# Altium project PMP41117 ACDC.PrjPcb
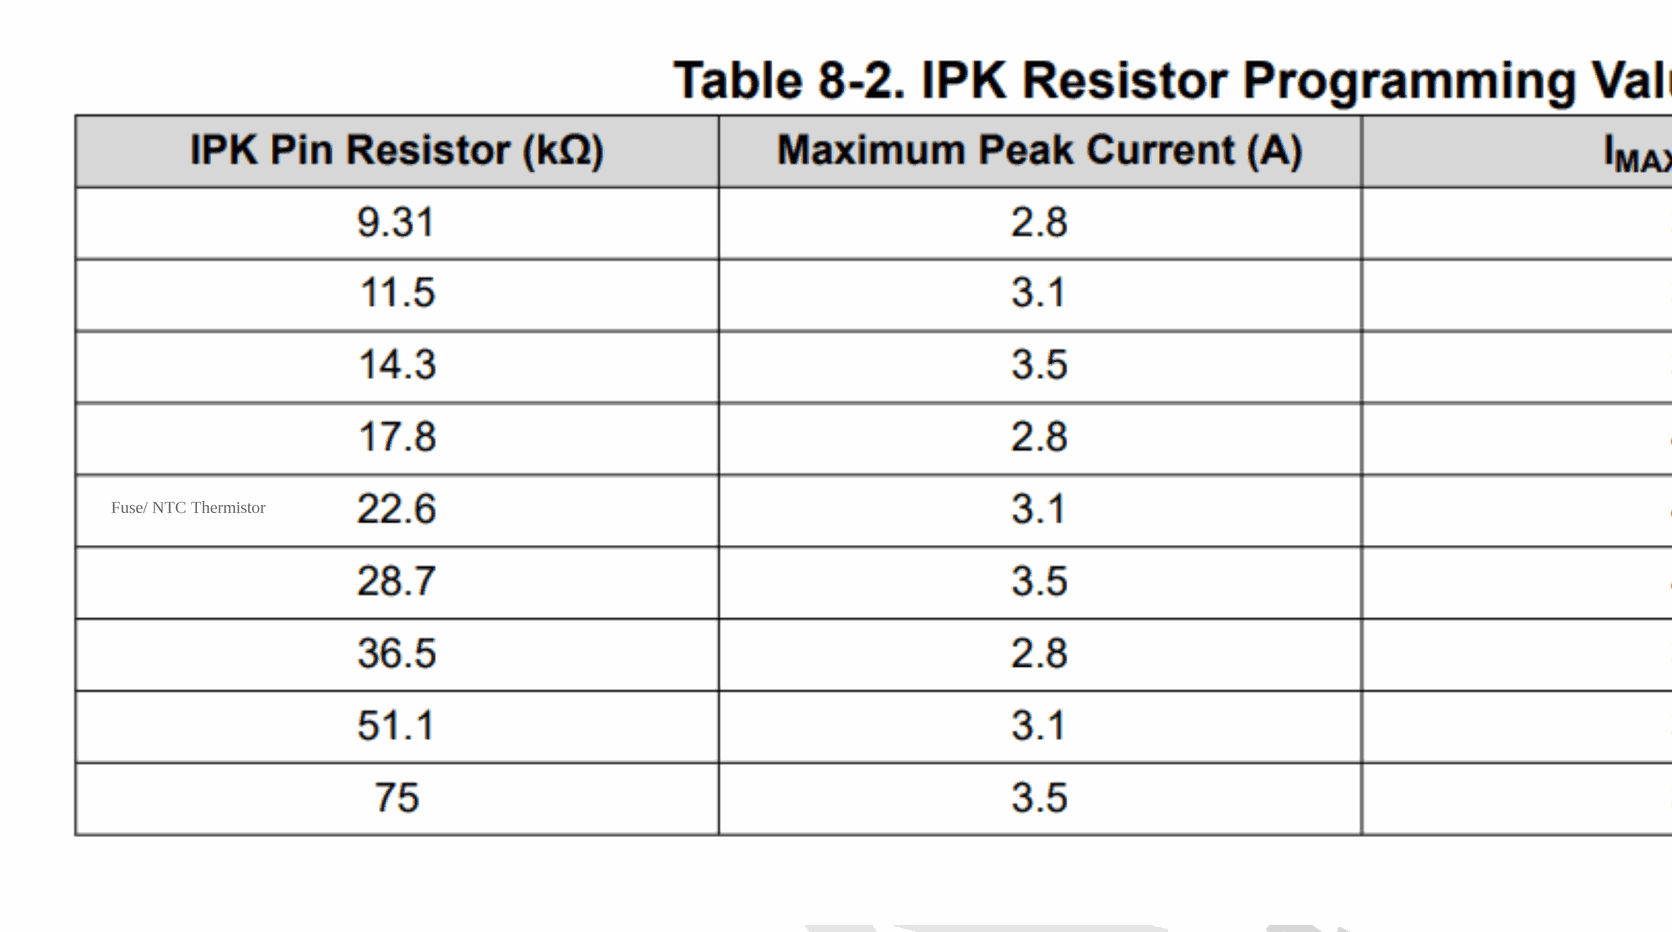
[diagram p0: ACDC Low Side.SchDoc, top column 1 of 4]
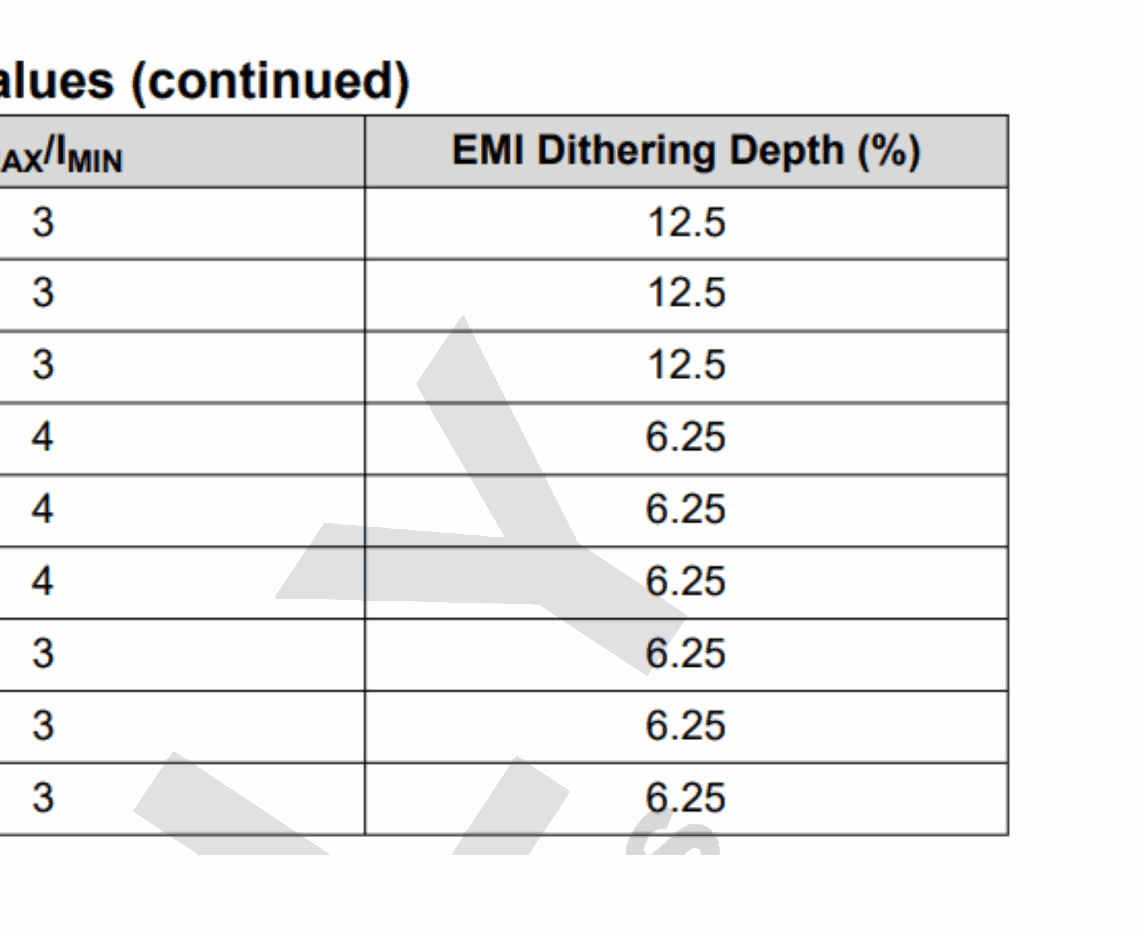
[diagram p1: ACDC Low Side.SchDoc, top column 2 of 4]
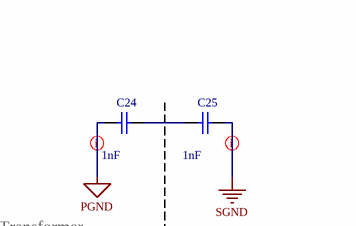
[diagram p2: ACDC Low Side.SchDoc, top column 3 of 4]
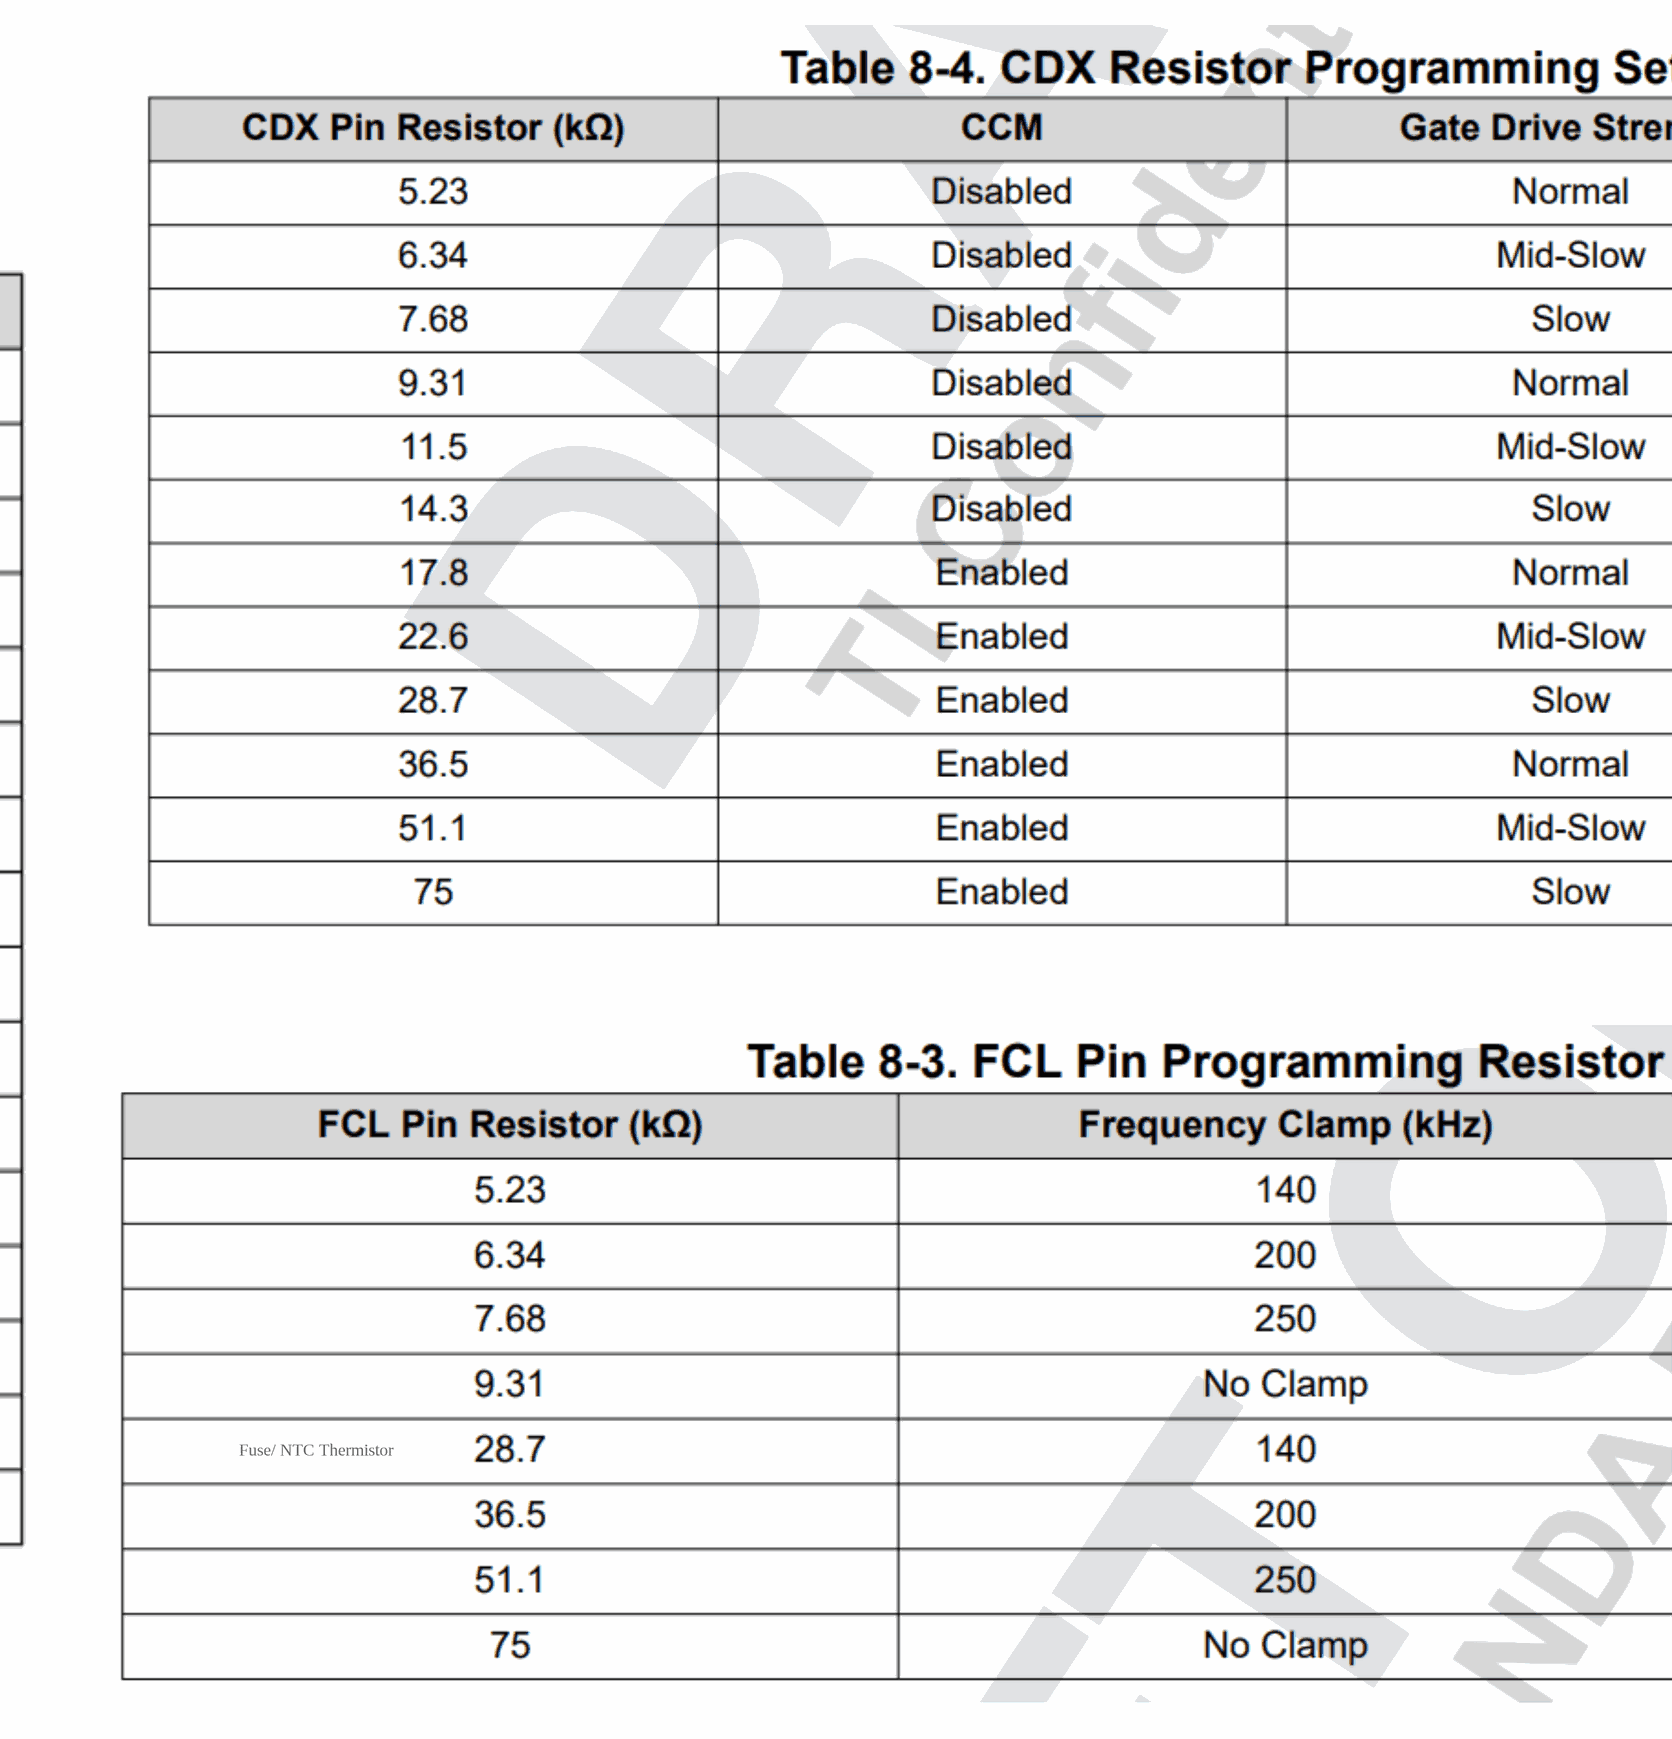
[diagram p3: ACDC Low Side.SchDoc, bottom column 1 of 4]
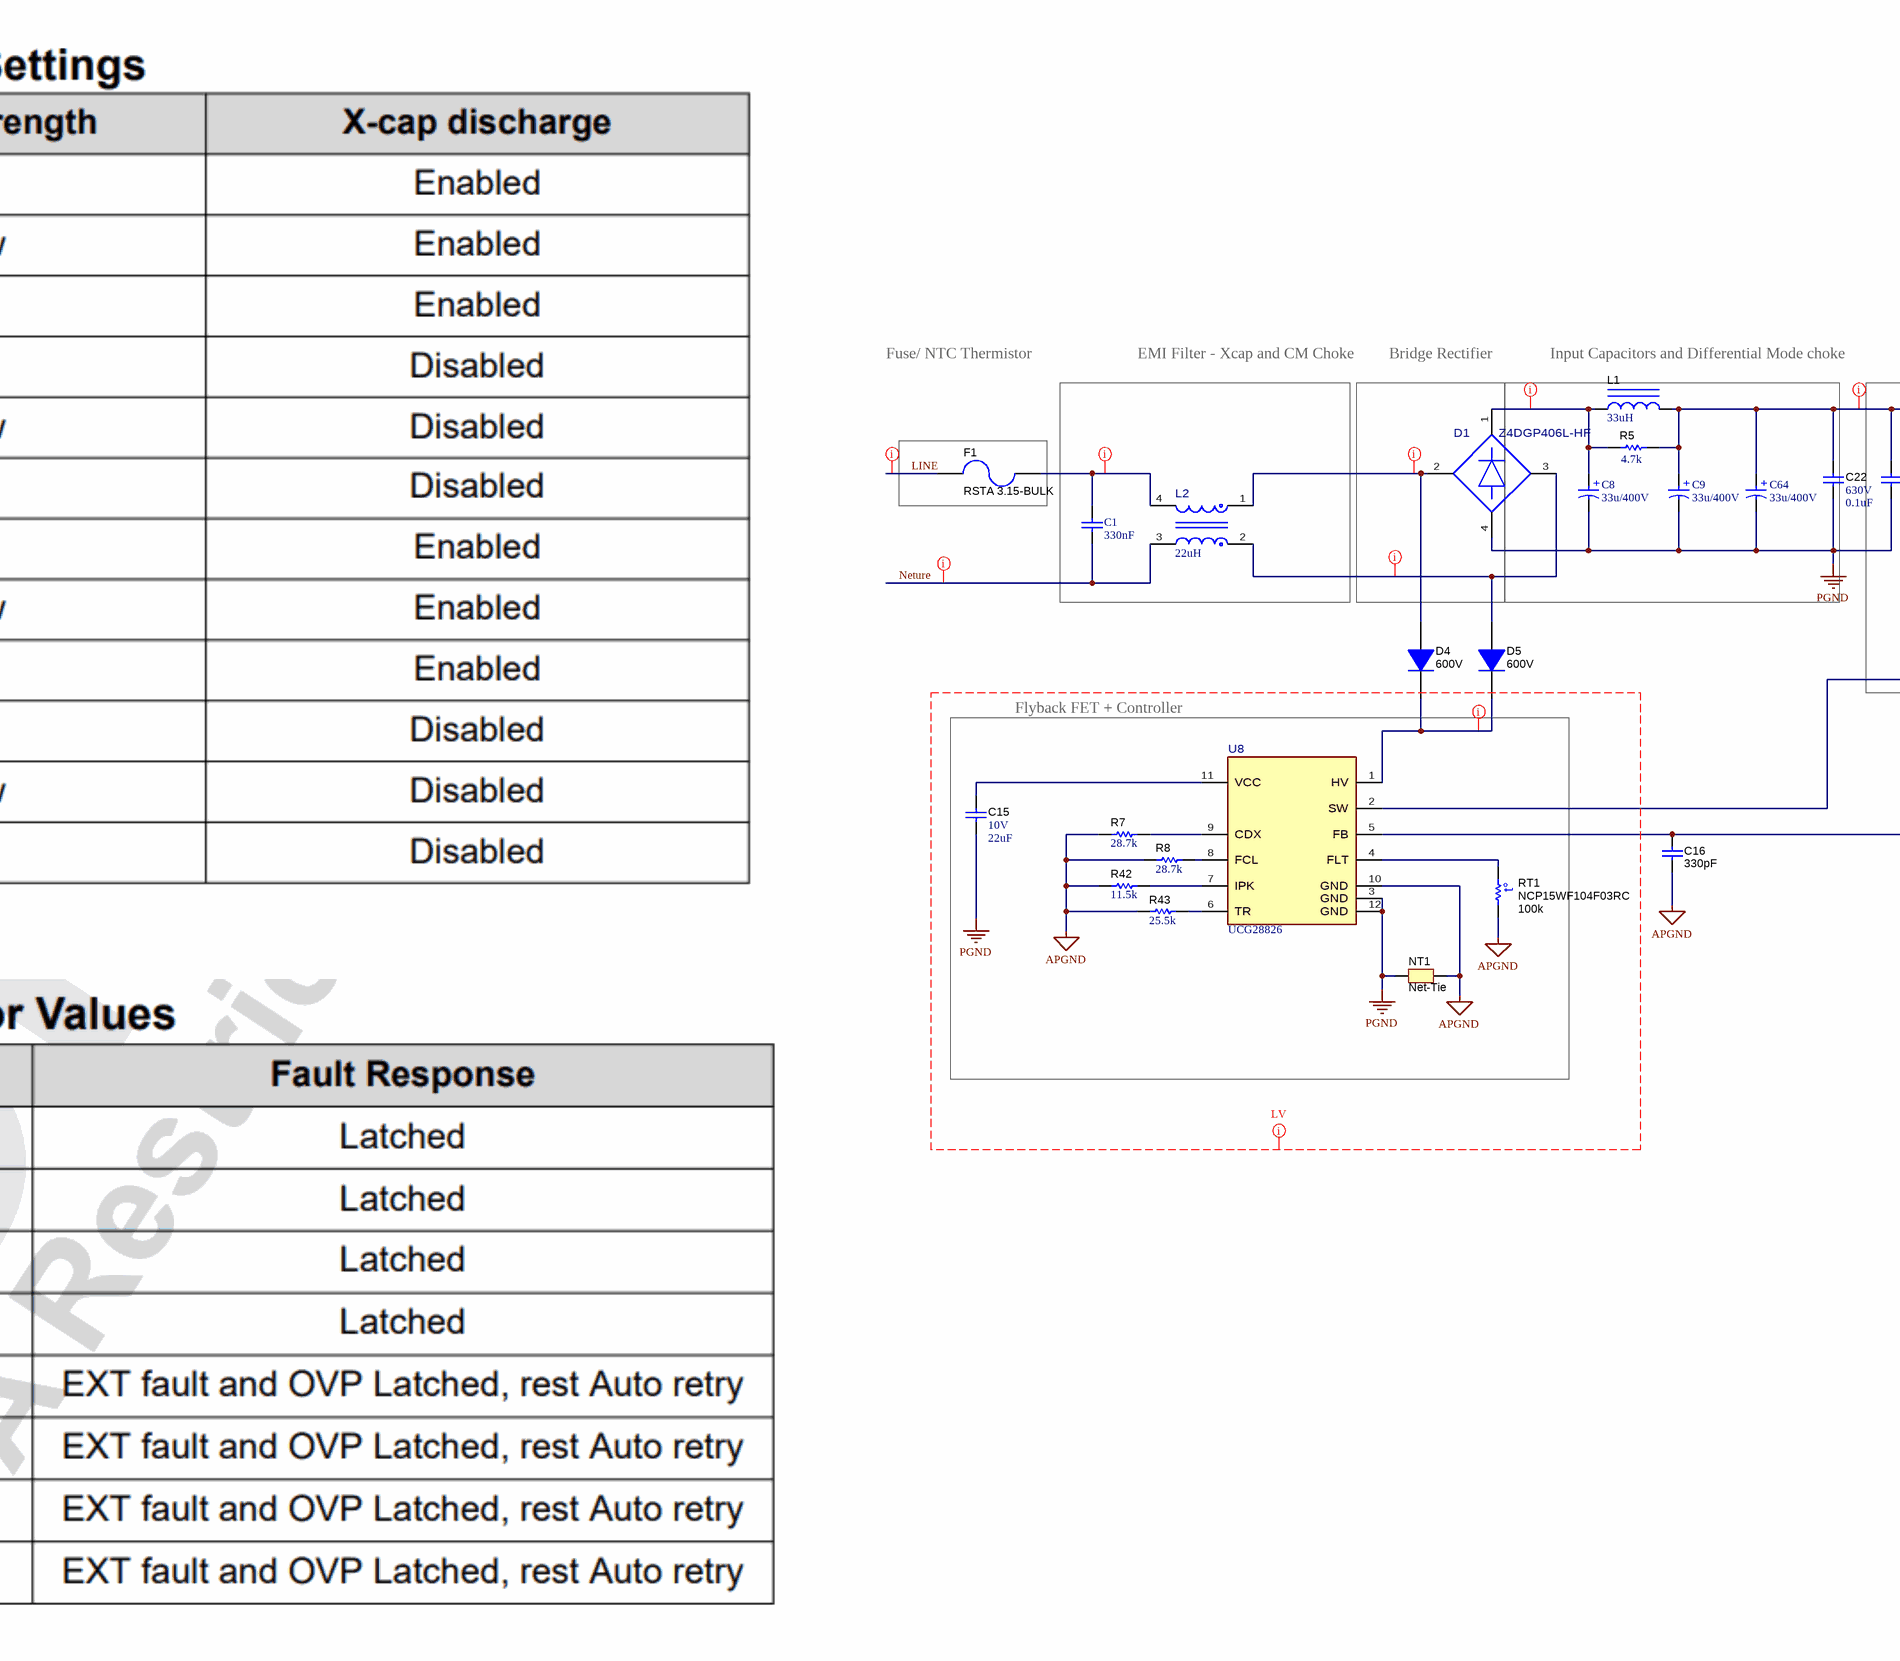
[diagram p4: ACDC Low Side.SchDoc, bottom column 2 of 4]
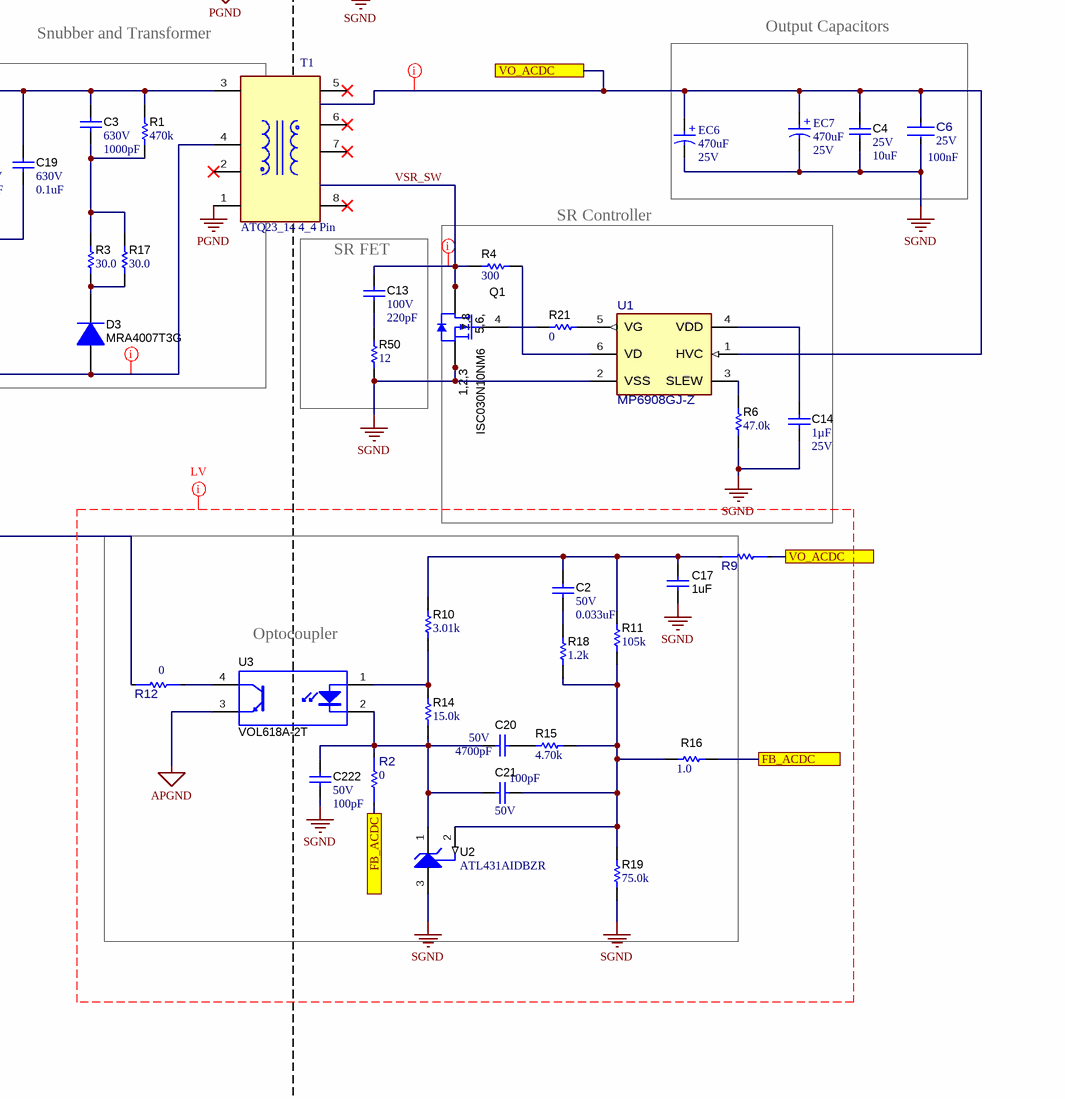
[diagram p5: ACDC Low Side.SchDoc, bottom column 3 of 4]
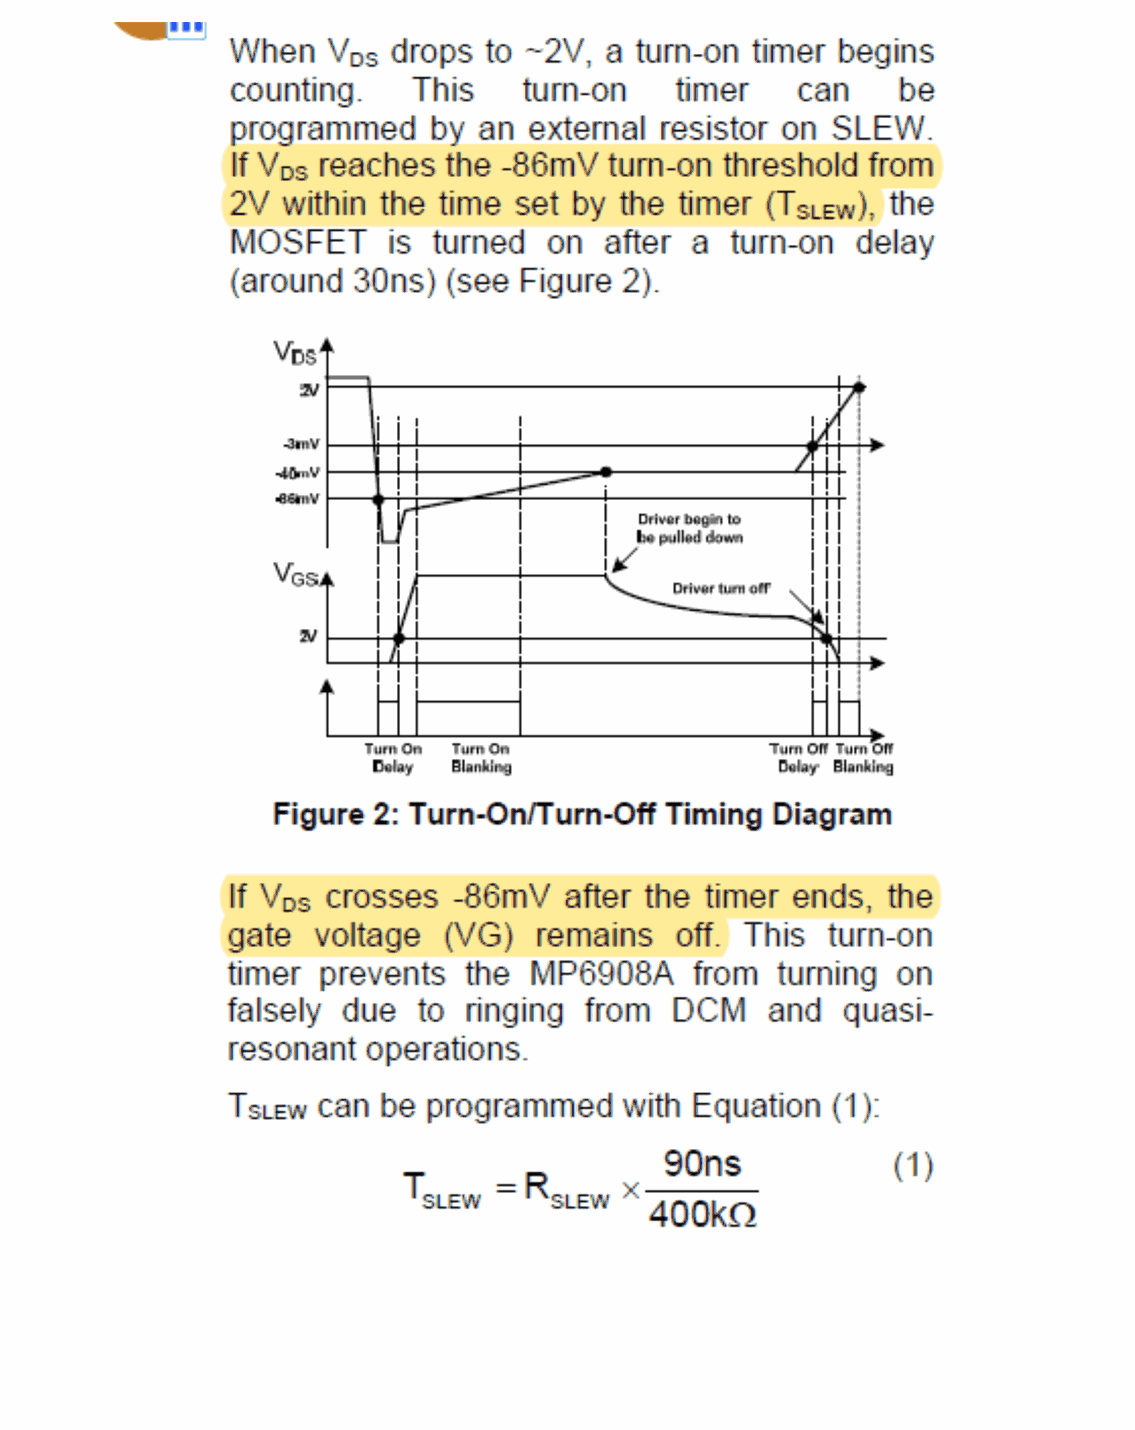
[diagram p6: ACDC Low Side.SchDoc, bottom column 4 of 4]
CopyrightYear: 2018; PCB_Layout: Max Wang; PCB_Rev: E1; PRJ_Customer: Public Release; PRJ_Engineer: Max Wang; PRJ_Number: PMP411145; PRJ_Title: Change in menu Project|Project Options|Parameters; SCH_Rev: E1; TechSupport: http://www.ti.com/support; TID: N/A
1 sheet, 59 parts. Net scope: flat (ports and power ports of the same name join across sheets).
Board file: PMP41117 ACDC.PcbDoc

## Sheet ACDC Low Side.SchDoc
size 431 x 279 mm; Date: Not shown in title block; ApprovedBy: Not shown in title block; CheckedBy: Not shown in title block; Author: Not shown in title block; CompanyName: Not shown in title block; Engineer: Not shown in title block; Organization: Not shown in title block; Address1: Not shown in title block; Address2: Not shown in title block; Address3: Not shown in title block; Address4: Not shown in title block; DocumentNumber: 1; Revision: Use project parameter SCH_Rev; SheetNumber: 1; SheetTotal: 1; PageSetup: Record=PageOptions¦CenterHorizontal=True¦CenterVertical=True¦PrintScale=1.00¦XCorrection=1.00¦YCorrection=1.00¦PrintKind=0¦BorderSize=5000000¦LeftOffset=0¦BottomOffset=0¦Orientation=2¦PaperLength=1000¦PaperWidth=1000¦Scale=100¦PaperSource=15¦PrintQuality=600¦MediaType=1¦DitherType=10¦PaperKind=Letter¦PrintScaleMode=1

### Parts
C1  value 330nF  [X CAP small form 7_10_8]  (hidden comment: MX2334KQ3B83YB2000R)
C2  VDC_V: 50V  ValueDisplayed: 0.033uF  [0402S]  (hidden comment: CGA2B3X7R1H333K050BB)
C3  VDC_V: 630V  ValueDisplayed: 1000pF  [1206]  (hidden comment: GRM31BR72J102KW01L)
C4  VDC_V: 25V  ValueDisplayed: 10uF  [0805_HV]  (hidden comment: TMK212BBJ106KG-T)
C6  VDC_V: 25V  Cap_F: 100nF  [FP-CGA3E2X8R1E104K080AD_0603-MFG]  (hidden comment: CGA3E2X8R1E104K080AD)
C8  33u/400V  [WCAP-ATG5_D8H16]
C9  33u/400V  [WCAP-ATG5_D8H16]
C13  VDC_V: 100V  ValueDisplayed: 220pF  [0603]  (hidden comment: GRM1885C2A221JA01D)
C14  Cap_F: 1µF  VDC_V: 25V  [0603S]  (hidden comment: CGA3E1X7R1E105K080AC)
C15  VDC_V: 10V  ValueDisplayed: 22uF  [0603]  (hidden comment: CL10A226MP8NUNE)
C16  ValueDisplayed: 330pF  [0402S]  (hidden comment: GRM155R71H331KA01D)
C17  ValueDisplayed: 1uF  [0603S]  (hidden comment: C1608X7R1E105K080AB)
C19  VDC_V: 630V  ValueDisplayed: 0.1uF  [1206_180]  (hidden comment: C3216X7T2W104M160AA)
C20  VDC_V: 50V  ValueDisplayed: 4700pF  [0402S]  (hidden comment: GRM155R71H472KA01D)
C21  VDC_V: 50V  ValueDisplayed: 100pF  [0402S]  (hidden comment: 885012205055)
C22  VDC_V: 630V  ValueDisplayed: 0.1uF  [1206_180]  (hidden comment: C3216X7T2W104M160AA)
C24  Cap_F: 1nF  [WCAP-CSSA_1808_L4.5W2H2]  (hidden comment: 8853522100131)
C25  Cap_F: 1nF  [WCAP-CSSA_1808_L4.5W2H2]  (hidden comment: 8853522100131)
C64  33u/400V  [WCAP-ATG5_D8H16]
C222  VDC_V: 50V  ValueDisplayed: 100pF  [0402S]  (hidden comment: 885012205055)
D1  Z4DGP406L-HF  [FP-Z4DGP406L-HF_SMT_8MM1_10MM5-MFG]
D3  MRA4007T3G  [SMA]
D4  value 600V  [SOD-123]  (hidden comment: ES1JFL)
D5  value 600V  [SOD-123]  (hidden comment: ES1JFL)
EC6  value 470uF  Voltage: 25V  [CE05.5P254L11]  (hidden comment: ECAP_LAYDOWN)
EC7  value 470uF  Voltage: 25V  [CE05.5P254L11]  (hidden comment: ECAP_LAYDOWN)
F1  RSTA 3.15-BULK  [FUSE]
L1  33uH  [WE-TI_5075]
L2  value 22uH  [LT 8*5 with pad]  (hidden comment: CMP-0088773-1)
NT1  Net-Tie  [Net-Tie_10milWide_30milLong]  (net tie, no BOM)
Q1  ISC030N10NM6  [PG-TDSON-8]
R1  ValueDisplayed: 470k  [0805_HV]  (hidden comment: CRCW0805470KJNEA)
R2  Res_ohm: 0  [FP-CRCW04020000Z0EDHP_0402-MFG]  (hidden comment: CRCW04020000Z0EDHP)
R3  ValueDisplayed: 30.0  [1206]  (hidden comment: RC1206FR-0730RL)
R4  ValueDisplayed: 300  [0603]  (hidden comment: RC0603FR-07300RL)
R5  ValueDisplayed: 4.7k  [1206]  (hidden comment: CRCW12064K70JNEA)
R6  ValueDisplayed: 47.0k  [0603]  (hidden comment: CRCW060347K0FKEA)
R7  ValueDisplayed: 28.7k  [0402]  (hidden comment: CRCW040228K7FKED)
R8  ValueDisplayed: 28.7k  [0402]  (hidden comment: CRCW040228K7FKED)
R9  CRCW04020000Z0EDHP  [FP-CRCW04020000Z0EDHP_0402-MFG]  (value not drawn)
R10  ValueDisplayed: 3.01k  [0402S]  (hidden comment: CRCW04023K01FKED)
R11  ValueDisplayed: 105k  [0603]  (hidden comment: RT0603DRE07105KL)
R12  Res_ohm: 0  [FP-CRCW04020000Z0EDHP_0402-MFG]  (hidden comment: CRCW04020000Z0EDHP)
R14  ValueDisplayed: 15.0k  [0402S]  (hidden comment: CRCW040215K0FKED)
R15  ValueDisplayed: 4.70k  [0402S]  (hidden comment: RC0402FR-074K7L)
R16  ValueDisplayed: 1.0  [0402]  (hidden comment: CRCW04021R00JNED)
R17  ValueDisplayed: 30.0  [1206]  (hidden comment: RC1206FR-0730RL)
R18  ValueDisplayed: 1.2k  [0402S]  (hidden comment: CRCW04021K20JNED)
R19  ValueDisplayed: 75.0k  [0603]  (hidden comment: RT0603DRE0775KL)
R21  ValueDisplayed: 0  [0201]  (hidden comment: CRCW02010000Z0ED)
R42  ValueDisplayed: 11.5k  [0402]  (hidden comment: CRCW040211K5FKED)
R43  ValueDisplayed: 25.5k  [0402]  (hidden comment: CRCW040225K5FKED)
R50  ValueDisplayed: 12  [0603]  (hidden comment: CRCW060312R0JNEA)
RT1  NCP15WF104F03RC  value 100k  [0402S]
T1  ATQ23_14 4_4 Pin  [ATQ23.9_13.8_Remove Flywire]
U1  MP6908GJ-Z  [FP-MP6908GJ-Z_TSOT23-6-MFG]
U2  ATL431AIDBZR  [DBZ0003A_N]
U3  VOL618A-2T  [SOP254P1020X230-4]
U8  UCG28826  [REZ0012A-MFG]

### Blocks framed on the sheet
Output Capacitors: C4 C6 EC6 EC7
SR Controller: C14 Q1 R4 R6 R21 U1
SR FET: C13 R50
Flyback FET + Controller: C15 NT1 R7 R8 R42 R43 RT1 U8
Optocoupler: C2 C17 C20 C21 C222 R2 R10-R12 R14-R16 R18 R19 U2 U3

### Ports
FB_ACDC, VO_ACDC

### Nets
APGND: C16.2 NT1.2 R7.1 R8.1 R42.1 R43.1 RT1.1 U3.3(E) U8.10(GND)
PGND: C8.2(N) C9.2(N) C15.2 C19.2 C22.2 C24.1 C64.2(N) D1.4(-) NT1.1 T1.1 U8.3(GND) U8.12(GND)
SGND: C4.2 C6.2 C14.2 C17.1 C25.2 C222.1 EC6.2(N) EC7.2(N) Q1.1(S) Q1.2(S) Q1.3(S) R6.1 R19.1 R50.1 U1.2(VSS) U2.3(ANODE)
FB_ACDC: R2.1 R16.2 ; port FB_ACDC
LINE: F1.2
Neture: C1.1 L2.3
VO_ACDC: C4.1 C6.1 EC6.1(P) EC7.1(P) R9.2 U1.1(HVC) ; port VO_ACDC
VSR_SW: C13.1 Q1.5(D) Q1.6(D) Q1.7(D) Q1.8(D) Q1.9(D) R4.1
NetC1_2: C1.2 F1.1 L2.4
NetC2_1: C2.1 C17.2 R9.1 R10.2 R11.2
NetC2_2: C2.2 R18.2
NetC3_1: C3.1 R1.1 R3.2 R17.2
NetC3_2: C3.2 C9.1(P) C19.1 C22.1 C64.1(P) L1.2 R1.2 R5.2 T1.3
NetC8_1: C8.1(P) D1.1(+) L1.1 R5.1
NetC13_2: C13.2 R50.2
NetC14_1: C14.1 U1.4(VDD)
NetC15_1: C15.1 U8.11(VCC)
NetC16_1: C16.1 R12.1 U8.5(FB)
NetC20_1: C20.1 R15.1
NetC20_2: C20.2 C21.2 C222.2 R2.2 R14.1 U2.1(CATHODE) U3.2(K)
NetC21_1: C21.1 R11.1 R15.2 R16.1 R18.1 R19.2 U2.2(REF)
NetC24_2: C24.2 C25.1
NetD1_2: D1.2(1_~) D4.2(A) L2.1
NetD1_3: D1.3(2_~) D5.2(A) L2.2
NetD3_1: D3.1(K) R3.1 R17.1
NetD3_2: D3.2(A) T1.4 U8.2(SW)
NetD4_1: D4.1(K) D5.1(K) U8.1(HV)
NetQ1_4: Q1.4(G) R21.1
NetR4_2: R4.2 U1.6(VD)
NetR6_2: R6.2 U1.3(SLEW)
NetR7_2: R7.2 U8.9(CDX)
NetR8_2: R8.2 U8.8(FCL)
NetR10_1: R10.1 R14.2 U3.1(A)
NetR12_2: R12.2 U3.4(C)
NetR21_2: R21.2 U1.5(VG)
NetR42_2: R42.2 U8.7(IPK)
NetR43_2: R43.2 U8.6(TR)
NetRT1_2: RT1.2 U8.4(FLT)

Not connected (* = marked no-connect by the designer): T1 2* 5* 6* 7* 8*

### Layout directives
net class VAC: LINE, NetC1_2, NetD1_2, NetD1_3, Neture
net class High Voltage: NetC3_2, NetC8_1, NetD4_1
net class Switch Node: NetD3_2
net class PGND: PGND
net class SGND: SGND, VO_ACDC, VSR_SW
net class Low Voltage: APGND, PGND, SGND

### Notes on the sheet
- Fuse/ NTC Thermistor
- EMI Filter - Xcap and CM Choke
- Bridge Rectifier
- (near L1) Input Capacitors and Differential Mode choke
- Snubber and Transformer

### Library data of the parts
C1 = CMP-0112463-1: X2 Film Capacitor, THT, 330nF, 275V; Manufacturer: DongGuan Chengxi; Capacitance Tolerance: +/-10%; Dissipation Factor @100kHz: 2%; Dissipation Factor @10kHz: 0.2%; Dissipation Factor @1kHz: 0.1%; Insulation Resistance: 30000MOhm; Pitch: 10mm; Rate of Voltage Rise: 300V/us
C2 = CMP-0006329-2: CAP, CERM, 0.033 uF, 50 V, +/- 10%, X7R, AEC-Q200 Grade 1, 0402; Manufacturer: TDK; TaMin_C: -55°C; ESR_ohm: 98.477m; Polarized: N; SizeAreaWB_mm2: 3; Value1: 0.098477 ohm; U/M: EA; TaMax_C: 125°C; SizeZ_mm: 0.6; SizeX_mm: 1; SizeY_mm: 0.5; Cap_Case: 0402; AEC Qualified: Y; Cap_F: 33nF; IRMS_A: 530.78mA; AEC Category: Q200
C3 = CMP-0008909-2: CAP, CERM, 1000 pF, 630 V, +/- 10%, X7R, 1206; Manufacturer: MuRata; TaMin_C: -55°C; Polarized: N; SizeAreaWB_mm2: 10.92; Value1: Unknown; U/M: EA; Value: 1000pF; TaMax_C: 125°C; SizeZ_mm: 1.35; SizeX_mm: 3.2; SizeY_mm: 1.6; SizeArea_mm2: 5.12; Cap_F: 1nF; AEC Category: Q200
C4 = CMP-0008414-2: CAP, CERM, 10 uF, 25 V, +/- 10%, X5R, 0805; Manufacturer: Taiyo Yuden; TaMin_C: -55°C; Polarized: N; SizeAreaWB_mm2: 6.75; Value1: Unknown; U/M: EA; Value: 10uF; TaMax_C: 85°C; SizeZ_mm: 1.45; SizeX_mm: 2; SizeY_mm: 1.25; Cap_Case: 0805; SizeArea_mm2: 2.5; Cap_F: 10µF; AEC Category: Q200
C6 = CMP-0086497-1: 0.1µF ±10% 25V Ceramic Capacitor X8R 0603 (1608 Metric); Manufacturer: TDK Corporation; SizeZ_mm: 0.95mm; TempCo: 15%; AEC Grade: Grade 0; AEC Qualified: Yes; Symbol Name: SYM-CGA3E2X8R1E104K080AD; Value: 100nF
C8 C9 C64 = CMP-0116785-1: KCMD2002G330MF Aluminum Electrolytic Capacitor, Radial, THT, D8 x H20mm, 33µF, 400V; Manufacturer: Yongming; Capacitance Tolerance: +0%/-40%; Dissipation Factor: 15%; Endurance: 2000h; Leakage Current: 264uA; Match Code: WCAP-ATG5; Ripple Current: 200mA; Technical Reference: ATJE1602203400DSPA7B0LR; Value: 33uF
C13 = CMP-0007256-4: CAP, CERM, 220 pF, 100 V, +/- 5%, C0G/NP0, 0603; Manufacturer: MuRata; TaMin_C: -55°C; Polarized: N; SizeAreaWB_mm2: 4.68; Value1: Unknown; U/M: EA; Value: 220pF; TaMax_C: 125°C; SizeZ_mm: 1; SizeX_mm: 1.6; SizeY_mm: 0.8; SizeArea_mm2: 1.28; AEC Category: Q200
C14 = CMP-0076705-1: CAP, CERM, 1 µF, 25 V,+/- 10%, X7R, AEC-Q200 Grade 1, 0603; Manufacturer: TDK; SizeAreaWB_mm2: 4.68; SizeArea_mm2: 1.28; AEC Qualified: Y; AEC Category: Q200; Value: 1uF; TaMax_C: 125°C; SizeZ_mm: 1.0; AEC Grade: 1; Polarized: N; TaMin_C: -55°C; SizeY_mm: 0.8; U/M: EA; SizeX_mm: 1.6; Cap_Case: 1.6x0.8x0.8mm
C15 = CMP-0007108-2: CAP, CERM, 22 uF, 10 V, +/- 20%, X5R, 0603; Manufacturer: Samsung Electro-Mechanics; TaMin_C: -55°C; Polarized: N; SizeAreaWB_mm2: 4.68; Value1: Unknown; U/M: EA; Value: 22uF; TaMax_C: 85°C; SizeZ_mm: 1; SizeX_mm: 1.6; SizeY_mm: 0.8; SizeArea_mm2: 1.28; Cap_F: 22µF; AEC Category: Q200
C16 = CMP-0006687-2: CAP, CERM, 330 pF, 50 V, +/- 10%, X7R, 0402; Manufacturer: MuRata; TaMin_C: -55°C; Polarized: N; SizeAreaWB_mm2: 3; Value1: Unknown; U/M: EA; Value: 330pF; TaMax_C: 125°C; SizeZ_mm: 0.6; SizeX_mm: 1; SizeY_mm: 0.5; Cap_Case: 0402; Value2: 50V; AEC Category: Q200
C17 = CMP-0007040-4: CAP, CERM, 1 µF, 25 V, +/- 10%, X7R, 0603; Manufacturer: TDK; Polarized: N; CompType: Capacitor; Value: 1uF; U/M: EA; Cap_F: 1µF; Value1: Unknown; VDC_V: 25V; TaMin_C: -55°C; TaMax_C: 125°C; Cap_Case: 0603; AEC Category: Q200; SizeArea_mm2: 1.28; SizeAreaWB_mm2: 4.68; SizeX_mm: 1.6; SizeY_mm: 0.8; SizeZ_mm: 1
C19 C22 = CMP-0008729-1: CAP, CERM, 0.1 uF, 450 V, +/- 20%, X7T, 1206; Manufacturer: TDK; TaMin_C: -55°C; Polarized: N; SizeAreaWB_mm2: 10.92; Value1: Unknown; U/M: EA; Value: 0.1uF; TaMax_C: 125°C; SizeZ_mm: 1.8; SizeX_mm: 3.2; SizeY_mm: 1.6; Cap_Case: 1206; Value2: 450V; SizeArea_mm2: 5.12; Cap_F: 100nF; AEC Category: Q200
C20 = CMP-0006692-2: CAP, CERM, 4700 pF, 50 V, +/- 10%, X7R, 0402; Manufacturer: MuRata; TaMin_C: -55°C; Polarized: N; SizeAreaWB_mm2: 3; Value1: Unknown; U/M: EA; Value: 4700pF; TaMax_C: 125°C; SizeZ_mm: 0.6; SizeX_mm: 1; SizeY_mm: 0.5; Cap_Case: 0402; Cap_F: 4.7nF; AEC Category: Q200
C21 C222 = CMP-0006230-2: CAP, CERM, 100 pF, 50 V, +/- 10%, X7R, 0402; Manufacturer: Wurth Elektronik; TaMin_C: -55°C; Polarized: N; SizeAreaWB_mm2: 3; Value1: Unknown; U/M: EA; Value: 100pF; TaMax_C: 125°C; SizeZ_mm: 0.6; SizeX_mm: 1; SizeY_mm: 0.5; Cap_Case: 0402; AEC Category: Q200
C24 C25 = CMP-0119859-1: WCAP-CSSA Multilayer Ceramic Chip Safety Capacitor, size 1808, X7R Class II, 1nF, 250VAC; Manufacturer: Wurth Elektronik; Capacitance Tolerance: +/-10%; Case/Size Code: 1808; Dissipation Factor: 2.5%; Impulse Voltage: 5000VDC; Insulation Resistance: 10GOhm; Rated Voltage (AC): 250V; Safety Class: X1/Y2; Technical Reference: X7R1808102KE00IFCT1B000
D1 = CMP-0120719-1: Bridge Rectifier Single Phase Standard 600 V Surface Mount Z4-D; Manufacturer: Comchip; AEC Qualified: No; SizeZ_mm: 1.45mm; TJmax_C: 175°C; Vf_V: 600V; Cap_F: 45pF; Forward Current: 4A; Max Surge Forward Current: 150A; Peak Reverse Current: 0.08uA
D3 = CMP-0077082-2: Diode, Standard Recovery Rectifier, 1000 V, 1 A, AEC-Q101, SMA; Manufacturer: ON Semiconductor; Value2: 1.1V; TJmax_C: 175°C; SizeX_mm: 5.59; Green_Lifecycle: Active; Value1: 1A; Green_REACh: Passed; AEC Qualified: Y; AEC Category: Q101; SizeArea_mm2: 16.3228; SizeY_mm: 2.92; SizeAreaWB_mm2: 37.3428; Value: 1000V; RJC_CperW: 16.2; SizeZ_mm: 2.87; Vr_V: 1kV
D4 D5 = CMP-0029032-2: Diode, Switching, 600 V, 1 A, SOD-123; Manufacturer: ON Semiconductor; SizeY_mm: 1.7; Io_A: 1A; SizeAreaWB_mm2: 13.095; SizeArea_mm2: 6.545; Vf_V: 1V; TJmax_C: 150°C; SizeX_mm: 3.85; SizeZ_mm: 1.35; Green_Lifecycle: Active; Green_REACh: Passed
EC6 EC7 = ECAP_LAYDOWN: 25V/470uF D5.5*11mm; PartNumber: NPXC1001E471MJTM; Manufacturer: Yongming
F1 = Fuse: Fuse, 3.15 A, 250 VAC, 63 VDC, TH; Manufacturer: Bel Fuse; VAC_V: 250V; SizeAreaWB_mm2: 62.1; SizeArea_mm2: 33.4; MeltingTyp: 66; Irating_A: 3.15A; SizeZ_mm: 8.1; SizeY_mm: 4; VDC_V: 63V; SizeX_mm: 8.35
L1 = CMP-0064517-1: Inductor, Unshielded Drum Core, 6*12mm, 33 uH, 2 A, TH RL0612-330K-HF; Manufacturer: Huizhou Deli Electronics; Isat: 1.7A @ 10% inductance drop; Irms: 1.8A @ 40C rise; Green_Lifecycle: Active; SizeAreaWB_mm2: 64; DCR_ohm: 0.102; Green_REACh: Passed; Value1: 0.102 ohm; Material: Ferrite; Imax_A: 1.7A; SizeZ_mm: 8.5; SizeX_mm: 6; SizeArea_mm2: 36; Ind_H: 22µH; AEC Category: Q200
L2 = CMP-0088773-1: 8*5mm CM choke 22uH, 0.5 wire* 6T, TCB8X4X3-8R0MINX2-JS-HF; Manufacturer: Huizhou Deli Electronics; Imax_A: 3.6A; AEC Qualified: No; Tolerance_%: 30%; Test Frequency: 10kHz; DCR_ohm: 36m; SizeZ_mm: 20.2mm
NT1 = CMP-0078142-6: Single point connection between nets.
Q1 = CMP-0001046-2: MOSFET, N-CH, 100 V, 3.3mR, PG-TDSON-8; Alternate Manufacturer: None; Manufacturer: Infineon Technologies; SizeZ_mm: 1.12; ChType: N; Value2: 33 nC; VdsMax_V: 100; SizeX_mm: 5.99; SizeY_mm: 4.9; Vgs_V: 20V; QgTyp_nC: 33; Value: 150V; SizeArea_mm2: 29.351; AEC Category: Q101; IdsMax_A: 87A; SizeAreaWB_mm2: 55.131; U/M: EA
R1 = CMP-0020554-3: RES, 470 k, 5%, 0.125 W, AEC-Q200 Grade 0, 0805; Manufacturer: Vishay-Dale; Power_W: 125mW; TempCo: 200 ppm/C; Value: 470k; EIA_Code: E24; SizeX_mm: 2; SizeY_mm: 1.25; SizeZ_mm: 1.45; Value2: 0.125W; SizeArea_mm2: 2.5; AEC Qualified: Y; VDC_V: 150V; AEC Category: Q200; AEC Grade: 0
R2 R12 = CMP-0001606-1: RES Thick Film, 0Ω, 0.2W, 0402; Manufacturer: Vishay Dale; AEC Grade: Grade 0; AEC Qualified: Yes; Power_W: 200mW; SizeZ_mm: 0.4mm; VDC_V: 50V; Value: 0
R3 R17 = CMP-0018196-2: RES, 30.0, 1%, 0.25 W, 1206; Manufacturer: Yageo America; Power_W: 250mW; TempCo: 100 ppm/C; Value_Code: 30R0; U/M: EA; Value: 30.0; Res_ohm: 30; SizeX_mm: 3.2; SizeY_mm: 1.6; SizeZ_mm: 1.35; Value2: 0.25W; SizeArea_mm2: 5.12; VDC_V: 200V; AEC Category: Q200
R4 = CMP-0023013-5: RES, 300, 1%, 0.1 W, 0603; Manufacturer: Yageo; Power_W: 100mW; TempCo: 100 ppm/C; Value_Code: 300R; Value: 300; SizeX_mm: 1.6; SizeY_mm: 0.8; SizeZ_mm: 1; Value2: 0.1W; SizeArea_mm2: 1.28; AEC Qualified: N; VDC_V: 75V; AEC Category: Q200; SizeAreaWB_mm2: 4.68
R5 = CMP-0018689-2: RES, 4.7 k, 5%, 0.25 W, 1206; Manufacturer: Vishay-Dale; Power_W: 250mW; TempCo: 200 ppm/C; Value_Code: 4k70; U/M: EA; Value: 4.7k; EIA_Code: E24; SizeX_mm: 3.2; SizeY_mm: 1.6; SizeZ_mm: 1.35; Value2: 0.25W; SizeArea_mm2: 5.12; VDC_V: 200V; AEC Category: Q200
R6 = CMP-0022438-1: RES, 47.0 k, 1%, 0.1 W, AEC-Q200 Grade 0, 0603; Manufacturer: Vishay-Dale; Power_W: 100mW; TempCo: 100 ppm/C; Value_Code: 47k0; U/M: EA; Value: 47.0k; Res_ohm: 47k; SizeX_mm: 1.6; SizeY_mm: 0.8; SizeZ_mm: 1; Value2: 0.1W; SizeArea_mm2: 1.28; AEC Qualified: Y; VDC_V: 75V; AEC Grade: 0; AEC Category: Q200
R7 R8 = CMP-0026220-2: RES, 28.7 k, 1%, 0.063 W, AEC-Q200 Grade 0, 0402; Manufacturer: Vishay-Dale; Power_W: 63mW; TempCo: 100 ppm/C; Value_Code: 28k7; Value: 28.7k; EIA_Code: E96; SizeX_mm: 1; SizeY_mm: 0.5; SizeZ_mm: 0.6; Value2: 0.063W; AEC Qualified: Y; VDC_V: 50V; AEC Category: Q200; AEC Grade: 0
R9 = CMP-0001606-1: RES Thick Film, 0Ω, 0.2W, 0402; Manufacturer: Vishay Dale; AEC Grade: Grade 0; AEC Qualified: Yes; Power_W: 200mW; Res_ohm: 0; SizeZ_mm: 0.4mm; VDC_V: 50V; Value: 0
R10 = CMP-0026329-2: RES, 3.01 k, 1%, 0.063 W, AEC-Q200 Grade 0, 0402; Manufacturer: Vishay-Dale; Power_W: 63mW; TempCo: 100 ppm/C; Value_Code: 3k01; Value: 3.01k; EIA_Code: E96; SizeX_mm: 1; SizeY_mm: 0.5; SizeZ_mm: 0.6; Value2: 0.063W; AEC Qualified: Y; VDC_V: 50V; AEC Category: Q200; AEC Grade: 0
R11 = CMP-0024571-1: RES, 105 k, 0.5%, 0.1 W, 0603; Manufacturer: Yageo America; Power_W: 100mW; TempCo: 50 ppm/C; U/M: EA; Value: 105k; EIA_Code: E192; SizeX_mm: 1.6; SizeY_mm: 0.8; SizeZ_mm: 1; Value2: 0.1W; SizeArea_mm2: 1.28; VDC_V: 75V; AEC Category: Q200
R14 = CMP-0026027-3: RES, 15.0 k, 1%, 0.063 W, AEC-Q200 Grade 0, 0402; Manufacturer: Vishay-Dale; Power_W: 63mW; TempCo: 100 ppm/C; Value_Code: 15k0; Value: 15.0k; EIA_Code: E96; Res_ohm: 15k; SizeX_mm: 1; SizeY_mm: 0.5; SizeZ_mm: 0.6; Value2: 0.063W; AEC Qualified: Y; VDC_V: 50V; AEC Category: Q200; AEC Grade: 0
R15 = CMP-0026739-1: RES, 4.70 k, 1%, 0.0625 W, 0402; Manufacturer: Yageo America; Power_W: 62.5mW; TempCo: 100 ppm/C; Value_Code: 4k70; U/M: EA; Value: 4.70k; Res_ohm: 4.7k; SizeX_mm: 1; SizeY_mm: 0.5; SizeZ_mm: 0.6; AEC Qualified: N; VDC_V: 50V; AEC Category: Q200
R16 = CMP-0026866-2: RES, 1.0, 5%, 0.063 W, 0402; Manufacturer: Vishay-Dale; Power_W: 63mW; TempCo: 200 ppm/C; Value_Code: 1R00; U/M: EA; Value: 1.0; EIA_Code: E24; Res_ohm: 1; SizeY_mm: 0.5; SizeZ_mm: 0.6; Value2: 0.063W; VDC_V: 50V; AEC Category: Q200
R18 = CMP-0026854-1: RES, 1.2 k, 5%, 0.063 W, 0402; Manufacturer: Vishay-Dale; Power_W: 63mW; TempCo: 200 ppm/C; Value_Code: 1k20; U/M: EA; Value: 1.2k; EIA_Code: E24; SizeX_mm: 1; SizeY_mm: 0.5; SizeZ_mm: 0.6; Value2: 0.063W; VDC_V: 50V; AEC Category: Q200
R19 = CMP-0025557-3: RES, 75.0 k, 0.5%, 0.1 W, 0603; Manufacturer: Yageo America; Power_W: 100mW; TempCo: 50 ppm/C; Value_Code: 75k0; U/M: EA; Value: 75.0k; EIA_Code: E192; Res_ohm: 75k; SizeX_mm: 1.6; SizeY_mm: 0.8; SizeZ_mm: 1; Value2: 0.1W; SizeArea_mm2: 1.28; VDC_V: 75V; AEC Category: Q200
R21 = CMP-0027008-4: RES, 0, 5%, 0.05 W, 0201; Manufacturer: Vishay-Dale; Power_W: 50mW; TempCo: ppm/C; Value_Code: 0000; Value: 0; EIA_Code: E24; SizeX_mm: 0.6; SizeY_mm: 0.3; SizeZ_mm: 0.26; Value2: 0.05W; SizeArea_mm2: 0.18; AEC Qualified: N; AEC Category: Q200
R42 = CMP-0025977-1: RES, 11.5 k, 1%, 0.063 W, 0402; Manufacturer: Vishay-Dale; Power_W: 63mW; TempCo: 100 ppm/C; Value_Code: 11k5; U/M: EA; Value: 11.5k; EIA_Code: E96; SizeX_mm: 1; SizeY_mm: 0.5; SizeZ_mm: 0.6; Value2: 0.063W; VDC_V: 50V; AEC Category: Q200
R43 = CMP-0026201-1: RES, 25.5 k, 1%, 0.063 W, 0402; Manufacturer: Vishay-Dale; Power_W: 63mW; TempCo: 100 ppm/C; Value_Code: 25k5; U/M: EA; Value: 25.5k; EIA_Code: E96; SizeX_mm: 1; SizeY_mm: 0.5; SizeZ_mm: 0.6; Value2: 0.063W; VDC_V: 50V; AEC Category: Q200
R50 = CMP-0025712-2: RES, 12, 5%, 0.1 W, 0603; Manufacturer: Vishay-Dale; Power_W: 100mW; TempCo: 200 ppm/C; Value_Code: 12R0; U/M: EA; Value: 12; EIA_Code: E24; SizeX_mm: 1.6; SizeY_mm: 0.8; SizeZ_mm: 1; Value2: 0.1W; SizeArea_mm2: 1.28; VDC_V: 75V; AEC Category: Q200
RT1 = CMP-0002353-2: Thermistor NTC, 100k ohm, 1%, 0402; Manufacturer: MuRata; TaMax_C: 125°C; SizeX_mm: 1; SizeY_mm: 0.5; TaMin_C: -40°C; Power_W: 100mW; SizeZ_mm: 0.6; SizeAreaWB_mm2: 3; U/M: EA
T1 = ATQ23_14 4_4 Pin: PartNumber: ATQ23-14; Manufacturer: Fort Electronics
U1 = CMP-0086802-1: FAST TURN-OFF INTELLIGENT RECTIF; Manufacturer: Monolithic Power Systems; SizeZ_mm: 1mm
U2 = CMP-0066199-1: 2.5V Low Iq Adjustable Precision Shunt Regulator, DBZ0003A (SOT-23-3); Alternate Manufacturer: Texas Instruments; SizeAreaWB_mm2: 14.0; U/M: EA; SizeZ_mm: 1.12; SizeX_mm: 2.5; SizeY_mm: 3.0; SizeArea_mm2: 7.5; CompType: IC
U3 = CMP-0006160-3: Optocoupler, 5 kV, 63-125% CTR, SMT; Manufacturer: Vishay-Semiconductor; CTR (Max): 125%; SizeAreaWB_mm2: 74.42; CTR (Min): 63%; SizeZ_mm: 2.3; SizeX_mm: 10.2; SizeY_mm: 4.1; SizeArea_mm2: 41.82; Voltage_Isolation_Vrms: 5kV
U8 = CMP-0122264-1: Manufacturer: Texas Instruments; SizeZ_mm: 1mm; AEC Qualified: No; AEC Grade: NA; Standoff Height: 0mm

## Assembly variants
001: not fitted C222 R2 RT1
